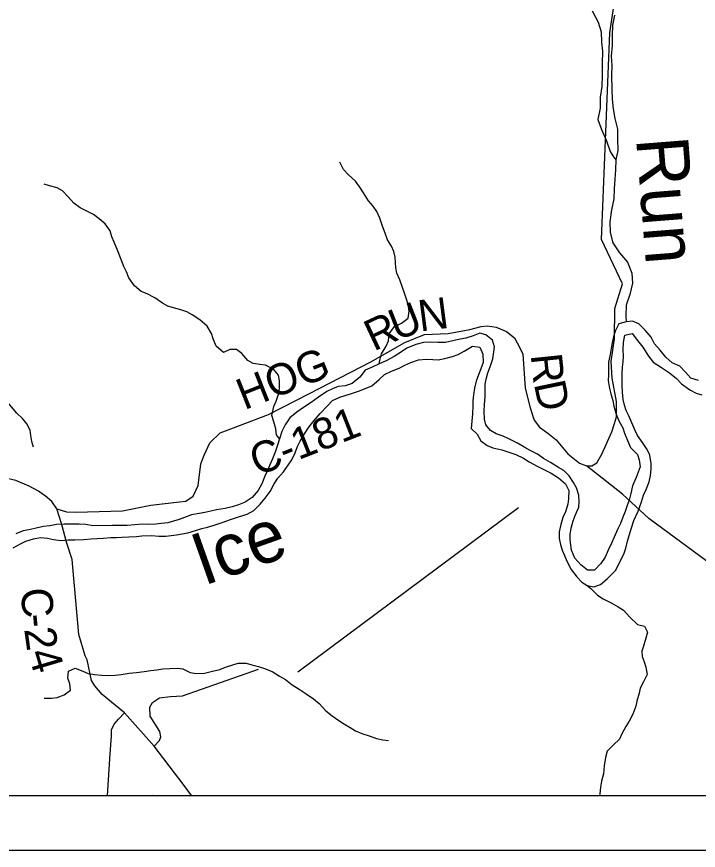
# Model space of a CAD drawing. Extents: x 0 to 34, y 0 to 22.
# Drawn here: x 4.209 to 5.45, y 14 to 15.517 of the extents above; entities that cross this region are included whole.
import ezdxf

# ---------------------------------------------------------------- set-up
doc = ezdxf.new("R2010")
doc.units = 0
for name, color, linetype in [('GM_X_City_Street', 7, 'Continuous'), ('GM_X_County_Road', 7, 'Continuous'), ('GM_X_County_Road_Text', 7, 'Continuous'), ('GM_X_Major_River', 7, 'Continuous'), ('GM_X_Major_River_Text', 7, 'Continuous'), ('GM_X_Minor_River', 7, 'Continuous'), ('GM_X_Township_Road', 7, 'Continuous'), ('SH_Data', 7, 'Continuous')]:
    doc.layers.add(name, color=color, linetype=linetype)

msp = doc.modelspace()

# ---------------------------------------------------------------- linework, layer by layer
at = {"layer": 'GM_X_City_Street'}
msp.add_line((4.4563, 14.1), (4.4558, 14.1007), dxfattribs=at)
for points in [[(4.5276, 14.1), (4.5144, 14.1177), (4.4594, 14.1895), (4.4058, 14.2501), (4.3646, 14.2837), (4.3518, 14.2994), (4.3454, 14.3093), (4.3373, 14.3469)], [(4.4594, 14.1895), (4.4695, 14.2002), (4.4718, 14.2068), (4.4698, 14.2162), (4.4521, 14.2439), (4.4518, 14.2606), (4.4564, 14.2689), (4.4693, 14.2776), (4.489, 14.2802), (4.5111, 14.2812), (4.6496, 14.3297)], [(4.3744, 14.1), (4.3796, 14.1755), (4.3817, 14.2078), (4.3818, 14.2191), (4.3867, 14.2295), (4.3947, 14.239), (4.4058, 14.2501)]]:
    msp.add_lwpolyline(points, dxfattribs=at)
at = {"layer": 'GM_X_County_Road'}
for points in [[(4.7424, 14.8318), (4.8541, 14.8893), (4.9157, 14.9245), (4.9514, 14.9388), (4.9948, 14.941), (5.0339, 14.9481), (5.0548, 14.9536), (5.0663, 14.9547), (5.0823, 14.9525), (5.101, 14.9443), (5.1158, 14.9327), (5.1252, 14.9146), (5.1307, 14.903), (5.1351, 14.8415), (5.1439, 14.8052), (5.151, 14.7832), (5.1609, 14.77), (5.1763, 14.7595), (5.1911, 14.7469), (5.2126, 14.7216), (5.234, 14.7045), (5.2467, 14.6996), (5.256, 14.7001), (5.2654, 14.7056), (5.2742, 14.721), (5.2929, 14.7617), (5.2978, 14.7771), (5.3011, 14.7892), (5.3011, 14.8167), (5.2934, 14.8596), (5.2912, 14.8898), (5.2973, 14.9311), (5.2983, 14.9864), (5.3122, 15.0314), (5.2739, 15.1116), (5.2892, 15.4883), (5.3073, 15.6088)], [(4.2824, 14.6216), (4.3001, 14.6164), (4.3169, 14.6153), (4.402, 14.6177), (4.4534, 14.628), (4.5054, 14.6342), (4.5171, 14.6355), (4.5307, 14.6444), (4.5397, 14.6643), (4.5444, 14.7034), (4.5506, 14.7191), (4.5609, 14.7417), (4.5797, 14.7602), (4.5989, 14.7671), (4.6674, 14.7931), (4.7424, 14.8318)], [(4.2583, 14.6471), (4.2488, 14.6537), (4.2323, 14.6626), (4.2077, 14.6729), (4.1865, 14.678), (4.1632, 14.6714), (4.1518, 14.6681), (4.1327, 14.6606), (4.1204, 14.652), (4.1121, 14.6401)], [(4.2824, 14.6216), (4.2731, 14.6352), (4.2611, 14.6451), (4.2583, 14.6471)], [(4.3115, 14.5153), (4.3102, 14.5293), (4.3006, 14.5588), (4.2909, 14.5951), (4.2824, 14.6216)], [(4.3373, 14.3469), (4.334, 14.3538), (4.3224, 14.3931), (4.3115, 14.5153)]]:
    msp.add_lwpolyline(points, dxfattribs=at)
at = {"layer": 'GM_X_Major_River'}
for points in [[(5.4504, 14.8554), (5.4368, 14.8592), (5.4266, 14.8705), (5.4164, 14.8811), (5.4028, 14.8876), (5.3911, 14.8978), (5.3805, 14.9107), (5.3703, 14.9221), (5.3643, 14.9342), (5.3533, 14.9471), (5.342, 14.9585), (5.3303, 14.9634), (5.3185, 14.9619), (5.3057, 14.9581), (5.2985, 14.9448), (5.2959, 14.9349), (5.2932, 14.9235), (5.2913, 14.9137), (5.2898, 14.9023), (5.2868, 14.8883), (5.2864, 14.8773), (5.2868, 14.8648), (5.286, 14.8549), (5.2883, 14.8405), (5.2909, 14.831), (5.2943, 14.8185), (5.2966, 14.8083), (5.3004, 14.7942), (5.3057, 14.7817), (5.3125, 14.7689), (5.3159, 14.7594), (5.3211, 14.7457), (5.3264, 14.7332), (5.3393, 14.7203), (5.3427, 14.7109), (5.3442, 14.698), (5.3408, 14.6885), (5.337, 14.6786), (5.3306, 14.6635), (5.3275, 14.6498), (5.3241, 14.6373), (5.3204, 14.6274), (5.317, 14.6168), (5.3128, 14.6062), (5.3083, 14.5948), (5.3033, 14.5838), (5.2969, 14.5702), (5.2928, 14.5603), (5.2859, 14.5463), (5.2807, 14.5338), (5.2727, 14.522)], [(5.2727, 14.522), (5.261, 14.5102), (5.2485, 14.5098), (5.2364, 14.5197), (5.2251, 14.5318), (5.219, 14.5462), (5.2168, 14.5652), (5.2168, 14.5747), (5.2187, 14.5864), (5.2225, 14.5997), (5.2262, 14.6092), (5.2327, 14.6247), (5.2334, 14.6342), (5.2327, 14.6463), (5.2285, 14.6596), (5.2229, 14.6695), (5.2149, 14.6816), (5.2055, 14.6911), (5.1956, 14.6971), (5.1809, 14.7062), (5.1684, 14.7134), (5.1575, 14.7214), (5.1442, 14.7278), (5.1344, 14.7335), (5.1212, 14.7411), (5.1049, 14.749), (5.0951, 14.7536), (5.0823, 14.7581), (5.0721, 14.7642), (5.0634, 14.7744), (5.0607, 14.785), (5.0603, 14.7991), (5.0611, 14.8116), (5.0622, 14.8252), (5.0622, 14.8351), (5.0622, 14.8484), (5.0638, 14.8578), (5.0672, 14.8692), (5.0721, 14.8817), (5.0762, 14.8946), (5.0781, 14.9071), (5.0789, 14.9166), (5.0755, 14.9284), (5.0634, 14.9386), (5.0521, 14.9416), (5.04, 14.9367), (5.0267, 14.9325), (5.0165, 14.9306), (5.0033, 14.9276), (4.9897, 14.9242), (4.9757, 14.9242), (4.9632, 14.9249), (4.95, 14.9241), (4.9356, 14.9207), (4.9198, 14.9139), (4.9099, 14.9071), (4.8963, 14.8991), (4.882, 14.8907), (4.8691, 14.8854), (4.8562, 14.8794), (4.8438, 14.8737), (4.8339, 14.8615), (4.82, 14.8498), (4.8071, 14.8456), (4.7946, 14.8441), (4.7844, 14.8403), (4.7738, 14.8353), (4.7587, 14.8251), (4.7451, 14.8152), (4.7315, 14.8061), (4.719, 14.7974), (4.7065, 14.7871), (4.6978, 14.7746), (4.6918, 14.7621), (4.6876, 14.7492), (4.6839, 14.7375), (4.6801, 14.725), (4.6752, 14.7128), (4.6702, 14.7018), (4.6661, 14.6916), (4.6612, 14.6813), (4.6555, 14.6673), (4.6491, 14.6548), (4.6377, 14.6423), (4.6252, 14.6339), (4.6131, 14.6286), (4.6018, 14.6252), (4.5886, 14.6222), (4.5731, 14.6199), (4.5625, 14.6172), (4.5515, 14.6149), (4.5417, 14.6134), (4.5277, 14.6104), (4.5149, 14.6058), (4.505, 14.6024), (4.4948, 14.599), (4.4846, 14.5963), (4.4725, 14.5948), (4.4623, 14.5937), (4.448, 14.5933), (4.4381, 14.5936)], [(5.2187, 14.511), (5.2289, 14.4977), (5.2379, 14.4882), (5.2478, 14.4822), (5.2598, 14.4799), (5.2719, 14.4841), (5.284, 14.4943), (5.2995, 14.5095), (5.3075, 14.5247), (5.315, 14.5406), (5.3181, 14.5501), (5.3215, 14.5626), (5.3241, 14.5728), (5.3283, 14.5869), (5.3328, 14.6001), (5.3408, 14.6172), (5.3464, 14.6343), (5.3506, 14.6464), (5.3551, 14.6566), (5.3604, 14.6707), (5.3631, 14.682), (5.3642, 14.6938), (5.3642, 14.7044), (5.3616, 14.7192), (5.3571, 14.7294), (5.3484, 14.7423), (5.3393, 14.7548), (5.3344, 14.7655), (5.3291, 14.778), (5.3234, 14.7908), (5.3189, 14.8003), (5.3159, 14.8102), (5.3132, 14.8208), (5.3121, 14.8341), (5.3117, 14.8466), (5.3117, 14.8682), (5.3121, 14.8792), (5.3132, 14.8894), (5.314, 14.8993), (5.3136, 14.9118), (5.314, 14.9243), (5.3163, 14.938), (5.3295, 14.9406), (5.3393, 14.9281), (5.3492, 14.916), (5.3597, 14.8997), (5.368, 14.8887), (5.3828, 14.8788), (5.3975, 14.8694), (5.4104, 14.8588), (5.4194, 14.8493), (5.4346, 14.8379), (5.4463, 14.8319), (5.4565, 14.8292)], [(4.3448, 14.5667), (4.3557, 14.5674), (4.3671, 14.5682), (4.3803, 14.5694), (4.3909, 14.5697), (4.4007, 14.5701), (4.4135, 14.5705), (4.4272, 14.5713), (4.4374, 14.5724), (4.4551, 14.5728), (4.468, 14.572), (4.4808, 14.5717), (4.4907, 14.5728), (4.5005, 14.5743), (4.5103, 14.5762), (4.5209, 14.5781), (4.5345, 14.5823), (4.5462, 14.5857), (4.5568, 14.5884), (4.5689, 14.5918), (4.5836, 14.5967), (4.5984, 14.6021), (4.6146, 14.6078), (4.629, 14.6119), (4.6411, 14.6184), (4.6528, 14.6298), (4.6619, 14.6411), (4.6706, 14.6529), (4.6782, 14.6673), (4.6846, 14.6776), (4.6952, 14.6889), (4.7035, 14.7011), (4.7103, 14.7106), (4.716, 14.7235), (4.7201, 14.7341), (4.7251, 14.7447), (4.733, 14.7583), (4.7413, 14.7701), (4.7508, 14.7822), (4.7617, 14.7951), (4.7746, 14.8084), (4.7844, 14.8187), (4.7973, 14.8251), (4.8071, 14.8278), (4.8207, 14.8323), (4.8313, 14.8357), (4.8426, 14.8399), (4.8559, 14.8452), (4.8691, 14.857), (4.8789, 14.8661), (4.8918, 14.8722), (4.9058, 14.8775), (4.9156, 14.8832), (4.9266, 14.8881), (4.9409, 14.8927), (4.9545, 14.8942), (4.9666, 14.8934), (4.9768, 14.8931), (4.9885, 14.8953), (5.0025, 14.8988), (5.0131, 14.9026), (5.0237, 14.9083), (5.0392, 14.9177), (5.0524, 14.9158), (5.0581, 14.9033), (5.0585, 14.8882), (5.0543, 14.8764), (5.0498, 14.8658), (5.046, 14.8537), (5.0426, 14.8415), (5.0407, 14.829), (5.0399, 14.8184), (5.0396, 14.8089), (5.0388, 14.7945), (5.0365, 14.768), (5.0475, 14.7574), (5.0543, 14.7452), (5.066, 14.7369), (5.0762, 14.7327), (5.0925, 14.7289), (5.1049, 14.7248), (5.1178, 14.7202), (5.1318, 14.7138), (5.1423, 14.707), (5.1567, 14.6994), (5.1824, 14.6865), (5.1953, 14.6782), (5.2085, 14.6672), (5.2142, 14.6551), (5.2138, 14.6399), (5.2123, 14.63), (5.2081, 14.6164), (5.2036, 14.6058), (5.1998, 14.5929), (5.1967, 14.5796), (5.1967, 14.5678), (5.199, 14.5565), (5.2024, 14.5466), (5.2066, 14.5364), (5.2115, 14.525), (5.2187, 14.511)], [(4.4381, 14.5936), (4.4245, 14.5925), (4.4105, 14.5914), (4.395, 14.5913), (4.3837, 14.591), (4.3482, 14.5909), (4.3353, 14.5932), (4.3228, 14.5936), (4.2956, 14.5936), (4.282, 14.5928), (4.2695, 14.5909), (4.2578, 14.5894), (4.2446, 14.5863), (4.2344, 14.5841), (4.2208, 14.5818), (4.2075, 14.5761)], [(4.203, 14.5507), (4.2162, 14.5579), (4.2261, 14.5625), (4.2397, 14.567), (4.2529, 14.5693), (4.2654, 14.5682), (4.2763, 14.5659), (4.2899, 14.564), (4.3032, 14.5651), (4.3153, 14.5651), (4.3308, 14.5659), (4.3448, 14.5667)]]:
    msp.add_lwpolyline(points, dxfattribs=at)
at = {"layer": 'GM_X_Minor_River'}
for points in [[(5.2568, 15.5283), (5.2681, 15.5074), (5.273, 15.4896), (5.2737, 15.4709), (5.2756, 15.4538), (5.2751, 15.4329), (5.2751, 15.4108), (5.2747, 15.3903), (5.2716, 15.3709), (5.2712, 15.3512), (5.2673, 15.3303), (5.2741, 15.312), (5.2828, 15.2915), (5.2895, 15.2721), (5.2948, 15.2643), (5.2997, 15.2568)], [(5.2977, 15.5199), (5.2942, 15.5017), (5.2934, 15.4831), (5.293, 15.4652), (5.2915, 15.4458), (5.2926, 15.4287), (5.2921, 15.4112), (5.2928, 15.3846), (5.2932, 15.3675), (5.2954, 15.3496), (5.2984, 15.3321), (5.3033, 15.3127), (5.3032, 15.2945), (5.3035, 15.274), (5.2997, 15.2568), (5.2993, 15.2386), (5.2981, 15.2215), (5.297, 15.204), (5.2961, 15.1858), (5.2919, 15.1656), (5.2889, 15.1439), (5.2896, 15.1246), (5.2948, 15.1059), (5.3065, 15.0877), (5.3212, 15.0705), (5.3291, 15.0504), (5.3302, 15.0325), (5.3256, 15.0116), (5.3188, 14.9922), (5.318, 14.9732), (5.3185, 14.9619)], [(4.8691, 14.8854), (4.8702, 14.8915), (4.8736, 14.9036), (4.8816, 14.9177), (4.8861, 14.9275), (4.8876, 14.9404), (4.8967, 14.9526), (4.9096, 14.9594), (4.9217, 14.9685), (4.9239, 14.9814), (4.922, 14.9935), (4.9186, 15.0034), (4.9152, 15.0144), (4.9118, 15.0242), (4.9066, 15.0383), (4.9013, 15.0508), (4.8994, 15.0602), (4.8986, 15.0701), (4.8983, 15.0796), (4.896, 15.0902), (4.8915, 15.0997), (4.8846, 15.111), (4.8801, 15.1236), (4.8752, 15.1361), (4.8703, 15.1505), (4.865, 15.163), (4.8582, 15.1728), (4.8499, 15.1823), (4.8408, 15.1967), (4.834, 15.2073), (4.8261, 15.2179), (4.8132, 15.2293), (4.8042, 15.2395), (4.7974, 15.2528)], [(4.6876, 14.7492), (4.6823, 14.7564), (4.6808, 14.767), (4.6774, 14.7799), (4.6737, 14.7917), (4.6774, 14.8076), (4.6816, 14.8175), (4.6861, 14.8304), (4.6877, 14.8406), (4.688, 14.8543), (4.6858, 14.8649), (4.6767, 14.8759), (4.6623, 14.8831), (4.6518, 14.8842), (4.64, 14.8861), (4.6298, 14.8918), (4.6193, 14.9046), (4.6094, 14.9118), (4.597, 14.9118), (4.5856, 14.9062), (4.5724, 14.9179), (4.5671, 14.9312), (4.5637, 14.941), (4.5558, 14.9539), (4.5429, 14.9657), (4.5289, 14.9748), (4.5191, 14.9801), (4.5081, 14.9838), (4.4949, 14.9876), (4.4847, 14.9907), (4.4745, 14.996), (4.4605, 15.0058), (4.4469, 15.013), (4.436, 15.0172), (4.4239, 15.0274), (4.4137, 15.0418), (4.4091, 15.0528), (4.4046, 15.0627), (4.3985, 15.0782), (4.394, 15.0892), (4.3865, 15.107), (4.3823, 15.1165), (4.3793, 15.1279), (4.3702, 15.1404), (4.3593, 15.1495), (4.349, 15.1574), (4.3249, 15.1696), (4.3131, 15.1779), (4.3029, 15.1893), (4.2927, 15.2003), (4.2829, 15.2056), (4.2693, 15.2097), (4.2591, 15.2124)], [(4.2396, 14.7336), (4.237, 14.7439), (4.2351, 14.7552), (4.2336, 14.7647), (4.2276, 14.7761), (4.2201, 14.786), (4.2095, 14.7959), (4.2, 14.8073), (4.191, 14.818), (4.1827, 14.8282), (4.1721, 14.8359), (4.1612, 14.845), (4.1532, 14.8496)], [(5.2478, 14.4822), (5.2542, 14.4765), (5.2663, 14.4647), (5.2769, 14.4575), (5.2916, 14.4503), (5.3041, 14.4435), (5.3139, 14.4371), (5.3252, 14.4242), (5.3396, 14.4109), (5.3524, 14.4083), (5.3577, 14.3973), (5.3547, 14.3863), (5.3505, 14.3719), (5.3471, 14.3624), (5.3479, 14.3529), (5.3513, 14.3431), (5.3543, 14.3332), (5.357, 14.3203), (5.3505, 14.3067), (5.3445, 14.2953), (5.3422, 14.2858), (5.3384, 14.2718), (5.3365, 14.2623), (5.3309, 14.2479), (5.3244, 14.235), (5.318, 14.2255), (5.3108, 14.2119), (5.3067, 14.2024), (5.2949, 14.1914), (5.2843, 14.1804), (5.2809, 14.169), (5.2787, 14.1538), (5.2775, 14.139), (5.2741, 14.1258), (5.2722, 14.1148), (5.2707, 14.1023), (5.2704, 14.1)], [(4.2593, 14.277), (4.2729, 14.277), (4.2827, 14.2781), (4.2959, 14.283), (4.3073, 14.2914), (4.3058, 14.3031), (4.3024, 14.3134), (4.3039, 14.3263), (4.316, 14.3316), (4.3296, 14.3263), (4.3394, 14.3221), (4.3511, 14.3202), (4.3636, 14.3187), (4.3757, 14.3183), (4.3885, 14.3187), (4.3995, 14.3199), (4.4139, 14.3225), (4.4271, 14.3237), (4.4411, 14.3256), (4.4532, 14.3271), (4.4645, 14.3286), (4.4751, 14.3305), (4.4883, 14.3309), (4.5019, 14.3313), (4.5118, 14.3302), (4.525, 14.3237), (4.536, 14.3218), (4.5511, 14.3226), (4.5658, 14.326), (4.5791, 14.3294), (4.5893, 14.3332), (4.6029, 14.3374), (4.6127, 14.3408), (4.6271, 14.3405), (4.6376, 14.3374), (4.6494, 14.3344), (4.6607, 14.331), (4.6743, 14.3253), (4.6879, 14.3173), (4.6989, 14.3109), (4.711, 14.3011), (4.7238, 14.2931), (4.7363, 14.2848), (4.7495, 14.2757), (4.7601, 14.267), (4.7718, 14.2541), (4.7835, 14.2446), (4.796, 14.2366), (4.8058, 14.2298), (4.8164, 14.2234), (4.8262, 14.2173), (4.8376, 14.2124), (4.8527, 14.2078), (4.864, 14.2033), (4.8757, 14.201), (4.8863, 14.1999)]]:
    msp.add_lwpolyline(points, dxfattribs=at)
at = {"layer": 'GM_X_Township_Road'}
for p, q in [((4.9777, 14.5161), (5.123, 14.6242)), ((4.7213, 14.3252), (4.9777, 14.5161))]:
    msp.add_line(p, q, dxfattribs=at)
msp.add_lwpolyline([(5.4903, 14.508), (5.4895, 14.5086), (5.4821, 14.5139), (5.4548, 14.534), (5.36, 14.604), (5.3119, 14.6481), (5.2467, 14.6996)], dxfattribs=at)
at = {"layer": 'SH_Data'}
for p, q in [((2.1, 14.1), (8.9, 14.1)), ((2, 14), (9, 14))]:
    msp.add_line(p, q, dxfattribs=at)

# ---------------------------------------------------------------- texts
at = {"layer": 'GM_X_County_Road_Text'}
for s, height, rotation, p in [('U', 0.0568, 21.4135, (4.9007, 14.927)), ('N', 0.0568, 7.3193, (4.9437, 14.9443)), ('R', 0.0568, 25.076, (4.8593, 14.9076)), ('HOG', 0.05682, 21.6888, (4.6238, 14.8009)), ('R', 0.0568, 275.9196, (5.1448, 14.9019)), ('D', 0.0568, 281.7902, (5.1506, 14.8493)), ('C-181', 0.05682, 21.4891, (4.6475, 14.6807)), ('C', 0.0568, 274.7906, (4.2163, 14.4758)), ('-', 0.0568, 275.4485, (4.2202, 14.4286)), ('2', 0.0568, 277.9658, (4.2228, 14.4027)), ('4', 0.0568, 286.5129, (4.2296, 14.359))]:
    msp.add_text(s, height=height, rotation=rotation, dxfattribs=at).set_placement(p)
at = {"layer": 'GM_X_Major_River_Text'}
for s, height, rotation, p in [('Run', 0.09467, 274.4922, (5.3367, 15.2958)), ('Ice', 0.09469, 19.4824, (4.5492, 14.481))]:
    msp.add_text(s, height=height, rotation=rotation, dxfattribs=at).set_placement(p)

doc.saveas('drawing.dxf')
